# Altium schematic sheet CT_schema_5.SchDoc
size 405 x 220 mm
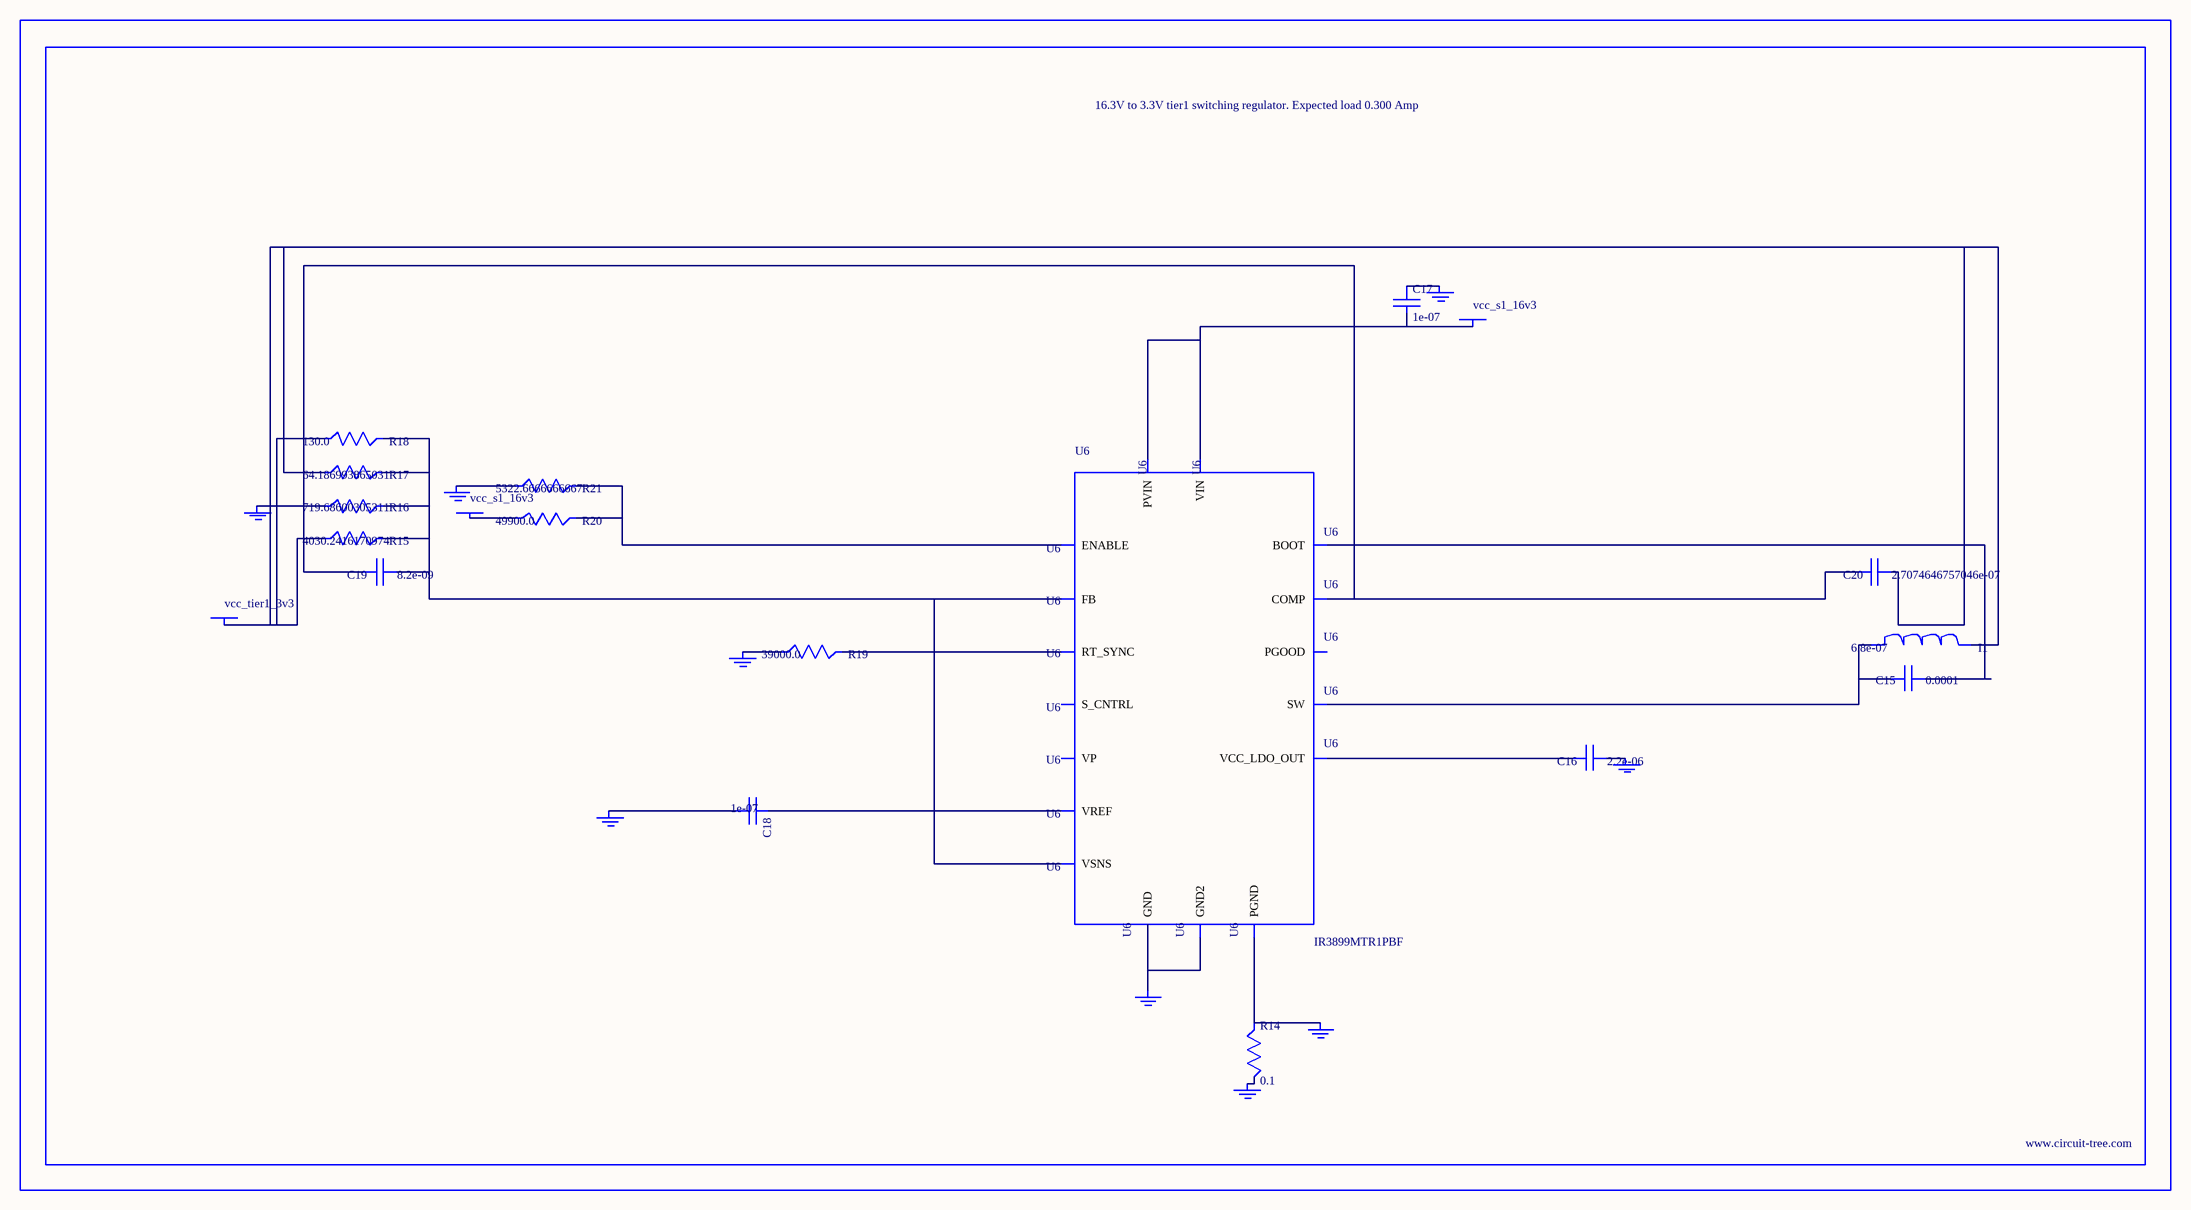
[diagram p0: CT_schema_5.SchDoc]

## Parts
BORDER4  (no value)
C15  0.0001  [C1210]
C16  2.2e-06  [C0603]
C17  1e-07  [C0402]
C18  1e-07  [C0402]
C19  8.2e-09  [C0402]
C20  2.7074646757046e-07  [R0603]
GND_INSTANCE_4_0  (no value)
GND_INSTANCE_4_1  (no value)
GND_INSTANCE_4_2  (no value)
GND_INSTANCE_4_3  (no value)
GND_INSTANCE_4_4  (no value)
GND_INSTANCE_4_5  (no value)
GND_INSTANCE_4_6  (no value)
GND_INSTANCE_4_7  (no value)
GND_INSTANCE_4_8  (no value)
I1  6.8e-07  [IND25X25CZ]
POWER_INSTANCE_4_0  vcc_s1_16v3
POWER_INSTANCE_4_1  vcc_s1_16v3
POWER_INSTANCE_4_2  vcc_tier1_3v3
R14  0.1  [R0603]
R15  4030.2416170974  [R0603]
R16  719.68600305311  [R0603]
R17  64.186993865031  [R0603]
R18  130.0  [R0603]
R19  39000.0  [R0603]
R20  49900.0  [R0603]
R21  5322.6666666667  [R0603]
U6  IR3899MTR1PBF  [IR3899MTR1PBF]

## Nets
NetC15_1: C15.1 U6.14(BOOT)
NetC15_2: C15.2 I1.1 U6.12(SW)
NetC16_1: C16.1 GND_INSTANCE_4_4.0(GND)
NetC16_2: C16.2 U6.10(VCC_LDO_OUT)
NetC17_1: C17.1 GND_INSTANCE_4_3.0(GND)
NetC17_2: C17.2 POWER_INSTANCE_4_0.0(PWR) U6.9(VIN) U6.13(PVIN)
NetC18_1: C18.1 U6.2(VREF)
NetC18_2: C18.2 GND_INSTANCE_4_1.0(GND)
NetC19_1: C19.1 R15.2 R16.2 R17.2 R18.2 U6.1(FB) U6.8(VSNS)
NetC19_2: C19.2 C20.2 U6.3(COMP)
NetC20_1: C20.1 I1.2 POWER_INSTANCE_4_2.0(PWR) R15.1 R17.1 R18.1
NetGND_INSTANCE_4_0_0: GND_INSTANCE_4_0.0(GND) R16.1
NetGND_INSTANCE_4_2_0: GND_INSTANCE_4_2.0(GND) R19.1
NetGND_INSTANCE_4_5_0: GND_INSTANCE_4_5.0(GND) R14.2
NetGND_INSTANCE_4_6_0: GND_INSTANCE_4_6.0(GND) R14.1 U6.11(PGND)
NetGND_INSTANCE_4_7_0: GND_INSTANCE_4_7.0(GND) R21.1
NetGND_INSTANCE_4_8_0: GND_INSTANCE_4_8.0(GND) U6.4(GND) U6.17(GND2)
NetPOWER_INSTANCE_4_1_0: POWER_INSTANCE_4_1.0(PWR) R20.1
NetR19_2: R19.2 U6.5(RT_SYNC)
NetR20_2: R20.2 R21.2 U6.15(ENABLE)

Not connected (* = marked no-connect by the designer): U6 6(S_CNTRL) 7(PGOOD) 16(VP)

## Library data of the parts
BORDER4 = BORDER_PAGE4
C15 = GRM32ER61A107ME20L
C16 = C0603C225K8RACTU
C17 C18 = C0402C104K3RACTU
C19 = C0402C822K3RAC
C20 = C20
GND_INSTANCE_4_0-GND_INSTANCE_4_8 = GND
I1 = IHLP2525CZERR68M01
POWER_INSTANCE_4_0-POWER_INSTANCE_4_2 = PWR
R14 = ERJ-3RSFR10V
R15 = R15
R16 = R16
R17 = R17
R18 = RC0603JR-07130RL
R19 = RC0603JR-0739KL
R20 = RC0603FR-0749K9
R21 = R21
